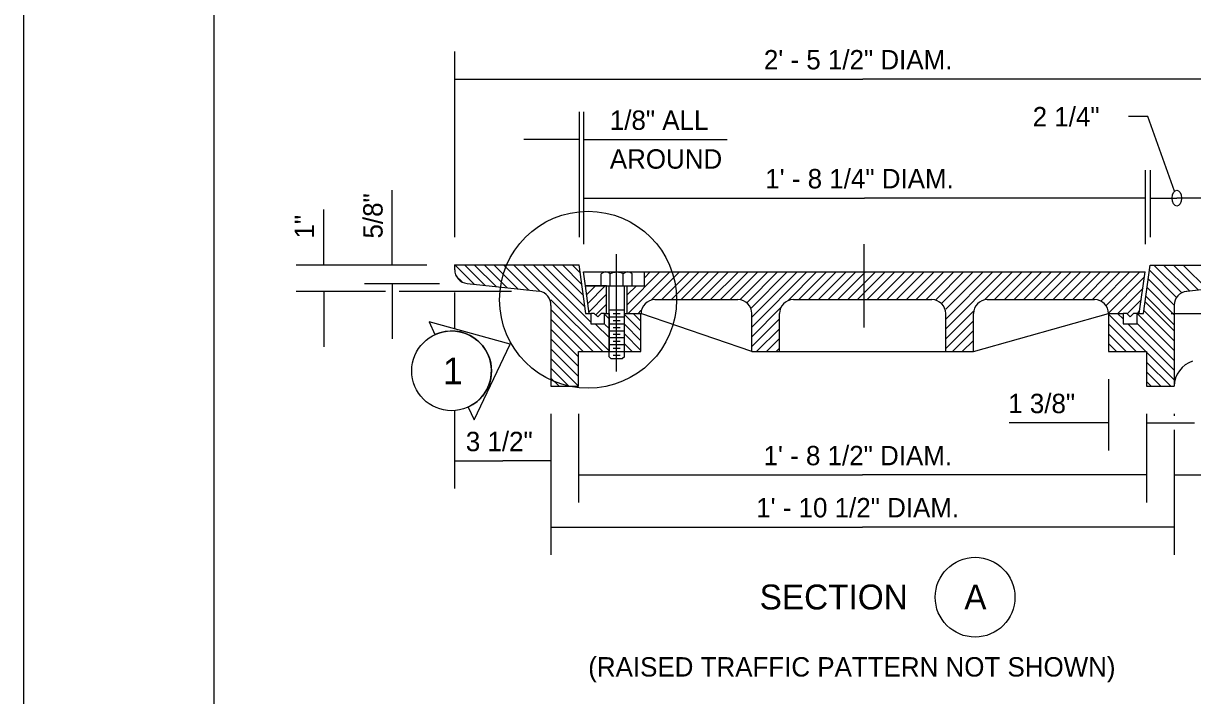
# Model space of a CAD drawing. Extents: x 99988 to 100172, y 99995 to 100047.
# Drawn here: x 99999.312 to 100003.533, y 100003.543 to 100005.97 of the extents above; entities that cross this region are included whole.
import ezdxf

# ---------------------------------------------------------------- set-up
doc = ezdxf.new("R2010")
doc.units = 0
for name, color, linetype in [('Level 1', 7, 'Continuous'), ('Level 15', 7, 'Continuous'), ('Level 2', 7, 'Continuous'), ('Level 20', 7, 'Continuous'), ('Level 9', 7, 'Continuous'), ('SH_GI_PlotLimits', 7, 'Continuous'), ('SH_GI_SheetBorder', 7, 'Continuous'), ('SH_RS_ConstructionNoteFlag', 7, 'Continuous'), ('SH_RS_DimensionLines', 7, 'Continuous')]:
    doc.layers.add(name, color=color, linetype=linetype)

msp = doc.modelspace()

# ---------------------------------------------------------------- linework, layer by layer
at = {"layer": 'Level 1'}
for p, q in [((100000.8693, 100005.0981), (100000.8693, 100005.0806)), ((100000.8693, 100005.0981), (100001.3193, 100005.0981)), ((100000.9395, 100005.0281), (100000.8695, 100005.0981)), ((100000.9791, 100005.0239), (100000.9048, 100005.0981)), ((100001.0186, 100005.0196), (100000.9401, 100005.0981)), ((100001.0583, 100005.0153), (100000.9755, 100005.0981)), ((100001.0979, 100005.0111), (100001.0109, 100005.0981)), ((100001.1375, 100005.0069), (100001.0462, 100005.0981)), ((100001.1771, 100005.0026), (100001.0816, 100005.0981)), ((100001.4293, 100004.7856), (100001.1168, 100005.0981)), ((100001.3622, 100004.8901), (100001.1522, 100005.0981)), ((100001.3396, 100004.9461), (100001.1876, 100005.0981)), ((100001.3342, 100004.9869), (100001.223, 100005.0981)), ((100001.3287, 100005.0277), (100001.2584, 100005.0981)), ((100001.3233, 100005.0686), (100001.2937, 100005.0981)), ((100001.3427, 100004.9226), (100001.3193, 100005.0981)), ((100001.3411, 100005.0225), (100001.3344, 100005.0725)), ((100001.3344, 100005.0725), (100001.5544, 100005.0725)), ((100001.3985, 100005.0225), (100001.3985, 100005.066)), ((100001.4308, 100005.0225), (100001.4308, 100005.066)), ((100001.4781, 100005.0225), (100001.4781, 100005.066)), ((100001.4919, 100004.9539), (100001.6105, 100005.0725)), ((100001.496, 100004.9225), (100001.6459, 100005.0725)), ((100001.5105, 100005.0225), (100001.5105, 100005.066)), ((100001.5544, 100005.0725), (100003.3619, 100005.0725)), ((100001.5544, 100005.0225), (100001.5544, 100005.0725)), ((100001.5544, 100005.0517), (100001.5751, 100005.0725)), ((100001.5813, 100004.9725), (100001.6812, 100005.0725)), ((100001.6167, 100004.9725), (100001.7166, 100005.0725)), ((100001.6519, 100004.9725), (100001.7519, 100005.0725)), ((100001.6873, 100004.9725), (100001.7873, 100005.0725)), ((100001.7226, 100004.9725), (100001.8226, 100005.0725)), ((100001.758, 100004.9725), (100001.858, 100005.0725)), ((100001.7934, 100004.9725), (100001.8933, 100005.0725)), ((100001.8288, 100004.9725), (100001.9287, 100005.0725)), ((100001.864, 100004.9725), (100001.9639, 100005.0725)), ((100001.8994, 100004.9725), (100001.9993, 100005.0725)), ((100001.9235, 100004.9613), (100002.0347, 100005.0725)), ((100001.9385, 100004.9408), (100002.0701, 100005.0725)), ((100001.9419, 100004.909), (100002.1054, 100005.0725)), ((100001.9419, 100004.8736), (100002.1407, 100005.0725)), ((100002.0719, 100004.9683), (100002.176, 100005.0725)), ((100002.1115, 100004.9725), (100002.2114, 100005.0725)), ((100002.1469, 100004.9725), (100002.2468, 100005.0725)), ((100002.1822, 100004.9725), (100002.2821, 100005.0725)), ((100002.2175, 100004.9725), (100002.3174, 100005.0725)), ((100002.2529, 100004.9725), (100002.3527, 100005.0725)), ((100002.2882, 100004.9725), (100002.3881, 100005.0725)), ((100002.3235, 100004.9725), (100002.4234, 100005.0725)), ((100002.3589, 100004.9725), (100002.4588, 100005.0725)), ((100002.3942, 100004.9725), (100002.4941, 100005.0725)), ((100002.4295, 100004.9725), (100002.5294, 100005.0725)), ((100002.4648, 100004.9725), (100002.5647, 100005.0725)), ((100002.5002, 100004.9725), (100002.6001, 100005.0725)), ((100002.5355, 100004.9725), (100002.6354, 100005.0725)), ((100002.5708, 100004.9725), (100002.6707, 100005.0725)), ((100002.6046, 100004.9709), (100002.7061, 100005.0725)), ((100002.6271, 100004.9581), (100002.7414, 100005.0725)), ((100002.6419, 100004.9376), (100002.7767, 100005.0725)), ((100002.6419, 100004.9022), (100002.8121, 100005.0725)), ((100002.6419, 100004.8668), (100002.8474, 100005.0725)), ((100002.7829, 100004.9725), (100002.8827, 100005.0725)), ((100002.8182, 100004.9725), (100002.9181, 100005.0725)), ((100002.8536, 100004.9725), (100002.9535, 100005.0725)), ((100002.8889, 100004.9725), (100002.9888, 100005.0725)), ((100002.9242, 100004.9725), (100003.0241, 100005.0725)), ((100002.9596, 100004.9725), (100003.0594, 100005.0725)), ((100002.9949, 100004.9725), (100003.0948, 100005.0725)), ((100003.0302, 100004.9725), (100003.1301, 100005.0725)), ((100003.0656, 100004.9725), (100003.1655, 100005.0725)), ((100003.101, 100004.9725), (100003.2008, 100005.0725)), ((100003.1363, 100004.9725), (100003.2361, 100005.0725)), ((100003.1717, 100004.9725), (100003.2715, 100005.0725)), ((100003.2017, 100004.9672), (100003.3068, 100005.0725)), ((100003.2206, 100004.9509), (100003.3421, 100005.0725)), ((100003.3406, 100004.9227), (100003.3619, 100005.0725)), ((100003.3561, 100004.9225), (100003.3794, 100005.0975)), ((100003.4752, 100004.9801), (100003.3769, 100005.0784)), ((100003.3794, 100005.0975), (100003.8169, 100005.0975)), ((100003.4938, 100004.9969), (100003.3932, 100005.0975)), ((100003.5225, 100005.0034), (100003.4285, 100005.0975)), ((100003.5544, 100005.0069), (100003.4638, 100005.0975)), ((100003.5864, 100005.0102), (100003.4992, 100005.0975)), ((100000.8958, 100005.0365), (100000.8753, 100005.0569)), ((100000.9141, 100005.0308), (100001.1746, 100005.0028)), ((100001.3544, 100004.9225), (100001.3411, 100005.0225)), ((100001.3411, 100005.0225), (100001.4179, 100005.0225)), ((100001.4169, 100005.0225), (100001.3411, 100005.0225)), ((100001.3413, 100005.0214), (100001.3424, 100005.0225)), ((100001.3454, 100004.9902), (100001.3777, 100005.0225)), ((100001.3496, 100004.959), (100001.4131, 100005.0225)), ((100001.3985, 100005.0225), (100001.5105, 100005.0225)), ((100001.4179, 100004.9225), (100001.4179, 100005.0225)), ((100001.4269, 100004.7667), (100001.4269, 100005.0225)), ((100001.4819, 100004.7667), (100001.4819, 100005.0225)), ((100001.4919, 100004.9225), (100001.4919, 100005.0225)), ((100001.4919, 100004.9893), (100001.5251, 100005.0225)), ((100001.4919, 100005.0225), (100001.5544, 100005.0225)), ((100003.2294, 100004.9243), (100003.3596, 100005.0545)), ((100003.4669, 100004.9176), (100003.3686, 100005.016)), ((100003.4669, 100004.953), (100003.3727, 100005.0472)), ((100003.7723, 100005.0302), (100003.5117, 100005.0022)), ((100001.3537, 100004.9278), (100001.4179, 100004.992)), ((100003.263, 100004.9225), (100003.3542, 100005.0138)), ((100003.4669, 100004.8822), (100003.3644, 100004.9847)), ((100001.4042, 100004.785), (100001.2169, 100004.9722)), ((100001.2169, 100004.951), (100001.2169, 100004.66)), ((100001.3688, 100004.785), (100001.2169, 100004.9369)), ((100001.3785, 100004.9172), (100001.4179, 100004.9567)), ((100001.4269, 100004.9355), (100001.4819, 100004.9355)), ((100001.5313, 100004.9225), (100001.5419, 100004.9332)), ((100001.5919, 100004.9725), (100001.8919, 100004.9725)), ((100001.9419, 100004.8383), (100002.0461, 100004.9426)), ((100002.0919, 100004.9725), (100002.5919, 100004.9725)), ((100002.6419, 100004.8314), (100002.7419, 100004.9315)), ((100002.7919, 100004.9725), (100003.1794, 100004.9725)), ((100003.297, 100004.9211), (100003.3486, 100004.9729)), ((100003.4669, 100004.8242), (100003.3561, 100004.935)), ((100003.4669, 100004.8594), (100003.3602, 100004.9661)), ((100003.4669, 100004.9525), (100003.4669, 100004.66)), ((100001.3335, 100004.785), (100001.2169, 100004.9015)), ((100001.3419, 100004.9225), (100001.3607, 100004.9225)), ((100001.4107, 100004.9225), (100001.4269, 100004.9225)), ((100001.4269, 100004.9036), (100001.4124, 100004.9182)), ((100001.4269, 100004.9225), (100001.4269, 100004.785)), ((100001.4269, 100004.9105), (100001.4819, 100004.9105)), ((100001.4419, 100004.9224), (100001.4669, 100004.9224)), ((100001.4419, 100004.8974), (100001.4669, 100004.8974)), ((100001.4819, 100004.9225), (100001.5419, 100004.9225)), ((100001.4819, 100004.785), (100001.4819, 100004.9225)), ((100001.5419, 100004.8594), (100001.4819, 100004.9194)), ((100001.5419, 100004.8947), (100001.5142, 100004.9225)), ((100001.5419, 100004.785), (100001.5419, 100004.9225)), ((100001.9419, 100004.785), (100001.5419, 100004.9225)), ((100001.9419, 100004.785), (100001.9419, 100004.9225)), ((100001.9419, 100004.8029), (100002.0419, 100004.903)), ((100002.0419, 100004.785), (100002.0419, 100004.9225)), ((100002.6419, 100004.785), (100002.6419, 100004.9225)), ((100002.6419, 100004.796), (100002.7419, 100004.8962)), ((100002.7419, 100004.785), (100002.7419, 100004.9225)), ((100002.7419, 100004.785), (100003.2294, 100004.9225)), ((100003.2294, 100004.9225), (100003.2294, 100004.785)), ((100003.2294, 100004.9225), (100003.2827, 100004.9225)), ((100003.2837, 100004.8659), (100003.2294, 100004.9201)), ((100003.2822, 100004.9027), (100003.2624, 100004.9225)), ((100003.3328, 100004.9215), (100003.3417, 100004.9306)), ((100003.3328, 100004.9225), (100003.3561, 100004.9225)), ((100003.4669, 100004.7888), (100003.3342, 100004.9215)), ((100001.3169, 100004.7661), (100001.2169, 100004.8661)), ((100001.4269, 100004.8355), (100001.3787, 100004.8832)), ((100001.4269, 100004.8683), (100001.4117, 100004.883)), ((100001.4269, 100004.8855), (100001.4819, 100004.8855)), ((100001.4269, 100004.8605), (100001.4819, 100004.8605)), ((100001.4419, 100004.8724), (100001.4669, 100004.8724)), ((100001.4419, 100004.8474), (100001.4669, 100004.8474)), ((100001.5419, 100004.824), (100001.4819, 100004.884)), ((100001.5419, 100004.7886), (100001.4819, 100004.8486)), ((100001.9594, 100004.785), (100002.0419, 100004.8676)), ((100002.6663, 100004.785), (100002.7419, 100004.8607)), ((100003.3292, 100004.785), (100003.2294, 100004.8847)), ((100003.2938, 100004.785), (100003.2294, 100004.8494)), ((100003.3646, 100004.785), (100003.2837, 100004.8659)), ((100003.4669, 100004.718), (100003.3018, 100004.8831)), ((100003.4669, 100004.7534), (100003.3335, 100004.8868)), ((100001.3169, 100004.7308), (100001.2169, 100004.8308)), ((100001.4269, 100004.8355), (100001.4819, 100004.8355)), ((100001.4269, 100004.8105), (100001.4819, 100004.8105)), ((100001.4419, 100004.8224), (100001.4669, 100004.8224)), ((100001.5102, 100004.785), (100001.4819, 100004.8133)), ((100001.9948, 100004.785), (100002.0419, 100004.8322)), ((100002.7017, 100004.785), (100002.7419, 100004.8254)), ((100003.2586, 100004.785), (100003.2294, 100004.8142)), ((100001.3169, 100004.6954), (100001.2169, 100004.7954)), ((100001.3169, 100004.66), (100001.3169, 100004.785)), ((100001.3169, 100004.785), (100001.4269, 100004.785)), ((100001.4269, 100004.7855), (100001.4819, 100004.7855)), ((100001.4332, 100004.7605), (100001.4269, 100004.7667)), ((100001.4419, 100004.7974), (100001.4669, 100004.7974)), ((100001.4419, 100004.7724), (100001.4669, 100004.7724)), ((100001.4819, 100004.7667), (100001.4757, 100004.7605)), ((100001.4819, 100004.785), (100001.5419, 100004.785)), ((100001.9419, 100004.785), (100002.0419, 100004.785)), ((100002.0301, 100004.785), (100002.0419, 100004.7968)), ((100002.0419, 100004.785), (100002.6419, 100004.785)), ((100002.6419, 100004.785), (100002.7419, 100004.785)), ((100003.2294, 100004.785), (100003.3669, 100004.785)), ((100003.3669, 100004.785), (100003.3669, 100004.66)), ((100003.4669, 100004.6826), (100003.3669, 100004.7826)), ((100001.3169, 100004.66), (100001.2169, 100004.76)), ((100001.2817, 100004.66), (100001.2169, 100004.7247)), ((100001.4332, 100004.7605), (100001.4757, 100004.7605)), ((100003.4542, 100004.66), (100003.3669, 100004.7472)), ((100001.2463, 100004.66), (100001.2169, 100004.6894)), ((100003.4188, 100004.66), (100003.3669, 100004.7119)), ((100001.2169, 100004.66), (100001.3169, 100004.66)), ((100003.3836, 100004.66), (100003.3669, 100004.6767)), ((100003.3669, 100004.66), (100003.4669, 100004.66))]:
    msp.add_line(p, q, dxfattribs=at)
for centre, radius, start, end in [((100000.9194, 100005.0805), 0.05, 180, 263.8922), ((100001.4146, 100005.0491), 0.0234, 46.2447, 133.7553), ((100001.4545, 100005.014), 0.0572, 65.5512, 114.4488), ((100001.4943, 100005.0492), 0.0233, 46.1679, 133.8321), ((100001.167, 100004.9534), 0.05, 357.2653, 81.2136), ((100003.5169, 100004.9525), 0.05, 96.0517, 180), ((100001.592, 100004.9225), 0.05, 90, 180), ((100001.892, 100004.9225), 0.05, 0, 90), ((100002.092, 100004.9225), 0.05, 90, 180), ((100002.592, 100004.9225), 0.05, 0, 90), ((100002.7919, 100004.9225), 0.05, 90, 180), ((100003.1794, 100004.9225), 0.05, 0, 90), ((100003.5614, 100004.6604), 0.0944, 107.4027, 180.2373)]:
    msp.add_arc(centre, radius, start, end, dxfattribs=at)
at = {"layer": 'Level 15'}
for p, q in [((100000.8693, 100005.8684), (100000.8693, 100005.1981)), ((100000.8693, 100005.7684), (100002.3431, 100005.7684)), ((100003.8169, 100005.7684), (100002.3431, 100005.7684)), ((100001.3193, 100005.6502), (100001.3193, 100005.1981)), ((100001.3344, 100005.6502), (100001.3344, 100005.1725)), ((100003.3619, 100005.4392), (100003.3619, 100005.1725)), ((100003.3794, 100005.4392), (100003.3794, 100005.1975)), ((100001.3344, 100005.3392), (100002.3482, 100005.3392)), ((100003.3619, 100005.3392), (100002.3482, 100005.3392)), ((100003.3794, 100005.3392), (100003.4761, 100005.3392)), ((100003.5729, 100005.3392), (100003.4761, 100005.3392)), ((100001.4531, 100004.7126), (100001.4531, 100005.1366)), ((100000.2966, 100005.0981), (100000.7693, 100005.0981)), ((100000.5442, 100005.0308), (100000.814, 100005.0308)), ((100000.2966, 100005.0028), (100000.6192, 100005.0028)), ((100000.6692, 100005.0028), (100001.0746, 100005.0028)), ((100000.8693, 100004.9981), (100000.8693, 100004.8672)), ((100003.4561, 100004.9225), (100004.2257, 100004.9225)), ((100003.2294, 100004.685), (100003.2294, 100004.4278)), ((100000.8693, 100004.5718), (100000.8693, 100004.2906)), ((100001.2169, 100004.56), (100001.2169, 100004.0517)), ((100001.3169, 100004.56), (100001.3169, 100004.2398)), ((100003.3669, 100004.56), (100003.3669, 100004.2398)), ((100003.4669, 100004.56), (100003.4669, 100004.5528)), ((100003.3669, 100004.5278), (100003.5394, 100004.5278)), ((100003.4669, 100004.5028), (100003.4669, 100004.0517)), ((100000.8693, 100004.3906), (100001.0431, 100004.3906)), ((100001.2169, 100004.3906), (100001.0431, 100004.3906)), ((100001.3169, 100004.3398), (100002.3419, 100004.3398)), ((100003.3669, 100004.3398), (100002.3419, 100004.3398)), ((100001.2169, 100004.1517), (100002.3419, 100004.1517)), ((100003.4669, 100004.1517), (100002.3419, 100004.1517))]:
    msp.add_line(p, q, dxfattribs=at)
msp.add_lwpolyline([(100003.4674, 100005.3638), (100003.372, 100005.6329), (100003.302, 100005.6329)], dxfattribs=at)
msp.add_ellipse((100003.4761, 100005.3392), major_axis=(0, -0.0288), ratio=0.57735, dxfattribs=at)
at = {"layer": 'Level 2'}
for points in [[(100001.3607, 100004.9225), (100001.3607, 100004.885), (100001.4107, 100004.885), (100001.4107, 100004.9225), (100001.3982, 100004.9225), (100001.3857, 100004.91), (100001.3732, 100004.9225), (100001.3607, 100004.9225)], [(100003.2828, 100004.9225), (100003.2828, 100004.885), (100003.3328, 100004.885), (100003.3328, 100004.9225), (100003.3203, 100004.9225), (100003.3078, 100004.91), (100003.2953, 100004.9225), (100003.2828, 100004.9225)]]:
    msp.add_lwpolyline(points, close=True, dxfattribs=at)
at = {"layer": 'Level 20'}
for p, q in [((100000.777, 100004.8926), (100000.7982, 100004.8463)), ((100001.0697, 100004.8123), (100000.777, 100004.8926)), ((100000.9394, 100004.5382), (100001.0697, 100004.8123)), ((100000.9182, 100004.5845), (100000.9394, 100004.5382))]:
    msp.add_line(p, q, dxfattribs=at)
for centre in [(100000.8582, 100004.7154), (100002.7479, 100003.8985)]:
    msp.add_circle(centre, 0.144, dxfattribs=at)
msp.add_arc((100000.8582, 100004.7154), 0.144, 294.6167, 114.6211, dxfattribs=at)
at = {"layer": 'Level 9'}
msp.add_line((100002.3465, 100005.1725), (100002.3465, 100004.8725), dxfattribs=at)
msp.add_circle((100001.3509, 100004.9722), 0.3194, dxfattribs=at)
at = {"layer": 'SH_GI_PlotLimits'}
msp.add_lwpolyline([(99999.3125, 99999.9375), (100015.8125, 99999.9375), (100015.8125, 100010.4375), (99999.3125, 100010.4375)], close=True, dxfattribs=at)
at = {"layer": 'SH_GI_SheetBorder'}
msp.add_line((100000, 100010.375), (100000, 100000), dxfattribs=at)
at = {"layer": 'SH_RS_DimensionLines'}
for p, q in [((100001.3193, 100005.5502), (100001.1193, 100005.5502)), ((100001.3344, 100005.5502), (100001.8532, 100005.5502)), ((100000.6442, 100005.0981), (100000.6442, 100005.3681)), ((100000.3966, 100005.0981), (100000.3966, 100005.2981)), ((100000.6442, 100005.0308), (100000.6442, 100004.8308)), ((100000.3966, 100005.0028), (100000.3966, 100004.8028)), ((100003.2294, 100004.5278), (100002.871, 100004.5278)), ((100003.4669, 100004.3398), (100003.6669, 100004.3398))]:
    msp.add_line(p, q, dxfattribs=at)

# ---------------------------------------------------------------- texts
at = {"layer": 'Level 20'}
for s, height, p in [('2\' - 5 1/2" DIAM.', 0.07, (100001.9855, 100005.8034)), ('2 1/4"', 0.07, (100002.9558, 100005.5979)), ('1\' - 8 1/4" DIAM.', 0.07, (100001.9905, 100005.3742)), ('1', 0.096, (100000.827, 100004.6673)), ('3 1/2"', 0.07, (100000.9096, 100004.4256)), ('1\' - 10 1/2" DIAM.', 0.07, (100001.9578, 100004.1867)), ('SECTION', 0.09, (100001.9701, 100003.8543)), ('A', 0.09, (100002.7089, 100003.8543)), ('(RAISED TRAFFIC PATTERN NOT SHOWN)', 0.07, (100001.3515, 100003.6122))]:
    msp.add_text(s, height=height, dxfattribs=at).set_placement(p)
msp.add_text('1\' - 8 1/2" DIAM.', height=0.07, rotation=360, dxfattribs=at).set_placement((100001.9843, 100004.3748))
at = {"layer": 'SH_RS_ConstructionNoteFlag'}
for s, p in [('1/8" ALL', (100001.4294, 100005.5852)), ('AROUND', (100001.4294, 100005.4452))]:
    msp.add_text(s, height=0.07, dxfattribs=at).set_placement(p)
for s, rotation, p in [('5/8"', 90, (100000.6092, 100005.1931)), ('1"', 90, (100000.3616, 100005.1931)), ('1 3/8"', 360, (100002.8675, 100004.5628))]:
    msp.add_text(s, height=0.07, rotation=rotation, dxfattribs=at).set_placement(p)

doc.saveas('drawing.dxf')
